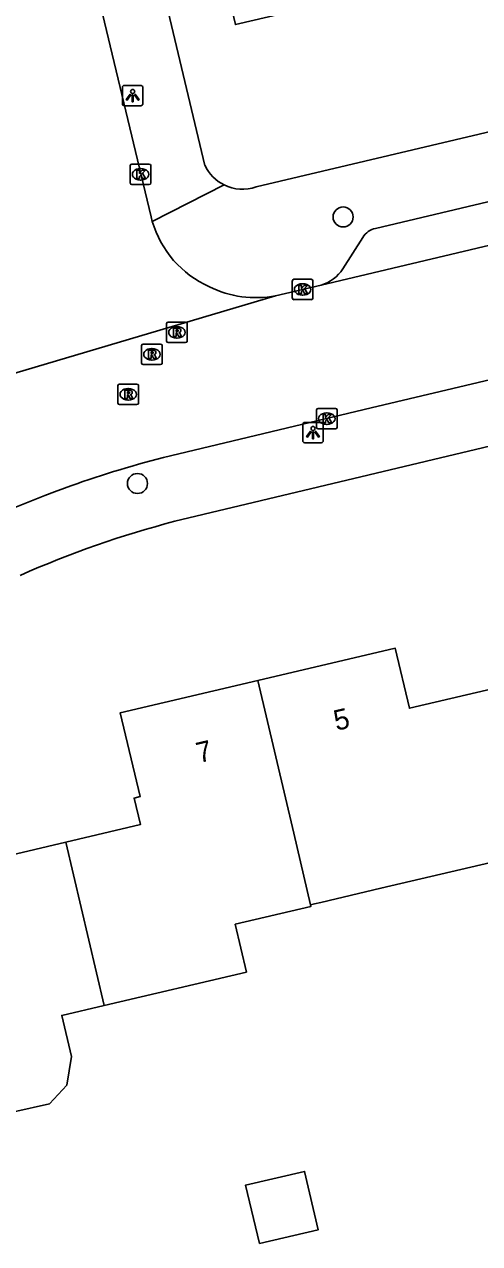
# Model space of a CAD drawing. Extents: x 157663 to 158496, y 379212 to 380934.
# Drawn here: x 158292.8 to 158315.1, y 380647.4 to 380707 of the extents above; entities that cross this region are included whole.
import ezdxf

# ---------------------------------------------------------------- set-up
doc = ezdxf.new("R2010")
doc.units = 0
for name, color, linetype in [('IMGEO_Boom', 7, 'Continuous'), ('IMGEO_Kolk', 7, 'Continuous'), ('IMGEO_Lichtpunt', 7, 'Continuous'), ('IMGEO_Pand', 7, 'Continuous'), ('IMGEO_Pand_nummerreeks', 7, 'Continuous'), ('IMGEO_Rijbaan_lokaal_open', 7, 'Continuous'), ('IMGEO_Rioolput', 7, 'Continuous'), ('IMGEO_Voetpad_open', 7, 'Continuous')]:
    doc.layers.add(name, color=color, linetype=linetype)

msp = doc.modelspace()

# ---------------------------------------------------------------- linework, layer by layer
at = {"layer": 'IMGEO_Boom'}
for centre in [(158308.4, 380697.582), (158298.353, 380684.548)]:
    msp.add_circle(centre, 0.489, dxfattribs=at)
at = {"layer": 'IMGEO_Kolk'}
for p, q in [((158298.004, 380699.245), (158298.004, 380700.097)), ((158298.079, 380700.171), (158298.931, 380700.171)), ((158298.492, 380699.951), (158298.517, 380699.951)), ((158299.005, 380700.097), (158299.005, 380699.245)), ((158298.931, 380699.171), (158298.079, 380699.171)), ((158298.515, 380699.391), (158298.49, 380699.391)), ((158305.919, 380693.613), (158305.919, 380694.465)), ((158305.994, 380694.539), (158306.846, 380694.539)), ((158306.92, 380694.465), (158306.92, 380693.613)), ((158306.407, 380694.319), (158306.432, 380694.319)), ((158306.846, 380693.539), (158305.994, 380693.539)), ((158306.43, 380693.759), (158306.405, 380693.759)), ((158307.102, 380687.294), (158307.102, 380688.146)), ((158307.177, 380688.22), (158308.029, 380688.22)), ((158307.59, 380688), (158307.615, 380688)), ((158308.103, 380688.146), (158308.103, 380687.294)), ((158308.029, 380687.22), (158307.177, 380687.22)), ((158307.613, 380687.44), (158307.588, 380687.44))]:
    msp.add_line(p, q, dxfattribs=at)
for points in [[(158298.004, 380699.245), (158298.004, 380700.097)], [(158298.079, 380700.171), (158298.931, 380700.171)], [(158298.325, 380699.871), (158298.448, 380699.871), (158298.448, 380699.72), (158298.578, 380699.871), (158298.742, 380699.871), (158298.596, 380699.72), (158298.749, 380699.471), (158298.597, 380699.471), (158298.512, 380699.635), (158298.448, 380699.568), (158298.448, 380699.471), (158298.325, 380699.471), (158298.325, 380699.871)], [(158299.005, 380700.097), (158299.005, 380699.245)], [(158298.931, 380699.171), (158298.079, 380699.171)], [(158305.919, 380693.613), (158305.919, 380694.465)], [(158305.994, 380694.539), (158306.846, 380694.539)], [(158306.92, 380694.465), (158306.92, 380693.613)], [(158306.24, 380694.239), (158306.363, 380694.239), (158306.363, 380694.088), (158306.493, 380694.239), (158306.657, 380694.239), (158306.511, 380694.088), (158306.664, 380693.839), (158306.512, 380693.839), (158306.427, 380694.003), (158306.363, 380693.936), (158306.363, 380693.839), (158306.24, 380693.839), (158306.24, 380694.239)], [(158306.846, 380693.539), (158305.994, 380693.539)], [(158307.102, 380687.294), (158307.102, 380688.146)], [(158307.177, 380688.22), (158308.029, 380688.22)], [(158307.423, 380687.92), (158307.546, 380687.92), (158307.546, 380687.769), (158307.676, 380687.92), (158307.84, 380687.92), (158307.694, 380687.769), (158307.847, 380687.52), (158307.695, 380687.52), (158307.61, 380687.684), (158307.546, 380687.617), (158307.546, 380687.52), (158307.423, 380687.52), (158307.423, 380687.92)], [(158308.103, 380688.146), (158308.103, 380687.294)], [(158308.029, 380687.22), (158307.177, 380687.22)]]:
    msp.add_lwpolyline(points, dxfattribs=at)
for centre, start, end in [((158298.081, 380700.095), 91.55205, 178.44795), ((158298.081, 380700.095), 91.55205, 178.44795), ((158298.929, 380700.095), 1.55205, 88.44795), ((158298.929, 380700.095), 1.55205, 88.44795), ((158298.081, 380699.247), 181.55205, 268.44795), ((158298.081, 380699.247), 181.55205, 268.44795), ((158298.929, 380699.247), 271.55205, 358.44795), ((158298.929, 380699.247), 271.55205, 358.44795), ((158305.996, 380694.463), 91.55205, 178.44795), ((158305.996, 380694.463), 91.55205, 178.44795), ((158306.844, 380694.463), 1.55205, 88.44795), ((158306.844, 380694.463), 1.55205, 88.44795), ((158305.996, 380693.615), 181.55205, 268.44795), ((158305.996, 380693.615), 181.55205, 268.44795), ((158306.844, 380693.615), 271.55205, 358.44795), ((158306.844, 380693.615), 271.55205, 358.44795), ((158307.179, 380688.144), 91.55205, 178.44795), ((158307.179, 380688.144), 91.55205, 178.44795), ((158308.027, 380688.144), 1.55205, 88.44795), ((158308.027, 380688.144), 1.55205, 88.44795), ((158307.179, 380687.296), 181.55205, 268.44795), ((158307.179, 380687.296), 181.55205, 268.44795), ((158308.027, 380687.296), 271.55205, 358.44795), ((158308.027, 380687.296), 271.55205, 358.44795)]:
    msp.add_arc(centre, 0.0765, start, end, dxfattribs=at)
for centre, major_axis, ratio, start_param, end_param in [((158298.491, 380699.671), (-0.387, 0.002), 0.722429, 4.712389, 7.853982), ((158298.516, 380699.671), (-0.39, 0.002), 0.717154, 1.570796, 4.712389), ((158306.406, 380694.039), (-0.387, 0.002), 0.722429, 4.712389, 7.853982), ((158306.431, 380694.039), (-0.39, 0.002), 0.717154, 1.570796, 4.712389), ((158307.589, 380687.72), (-0.387, 0.002), 0.722429, 4.712389, 7.853982), ((158307.614, 380687.72), (-0.39, 0.002), 0.717154, 1.570796, 4.712389)]:
    msp.add_ellipse(centre, major_axis=major_axis, ratio=ratio, start_param=start_param, end_param=end_param, dxfattribs=at)
at = {"layer": 'IMGEO_Lichtpunt'}
for p, q in [((158297.619, 380703.921), (158297.619, 380703.114)), ((158297.619, 380703.921), (158297.619, 380703.114)), ((158298.521, 380704.016), (158297.713, 380704.016)), ((158298.521, 380704.016), (158297.713, 380704.016)), ((158298.615, 380703.114), (158298.615, 380703.921)), ((158298.615, 380703.114), (158298.615, 380703.921)), ((158297.713, 380703.02), (158298.521, 380703.02)), ((158297.713, 380703.02), (158298.521, 380703.02)), ((158306.432, 380687.44), (158306.432, 380686.633)), ((158306.432, 380687.44), (158306.432, 380686.633)), ((158307.334, 380687.535), (158306.526, 380687.535)), ((158307.334, 380687.535), (158306.526, 380687.535)), ((158307.428, 380686.633), (158307.428, 380687.44)), ((158307.428, 380686.633), (158307.428, 380687.44)), ((158306.526, 380686.539), (158307.334, 380686.539)), ((158306.526, 380686.539), (158307.334, 380686.539))]:
    msp.add_line(p, q, dxfattribs=at)
for points in [[(158297.993, 380703.585), (158298.032, 380703.557), (158297.844, 380703.295), (158297.806, 380703.322), (158297.993, 380703.585)], [(158298.095, 380703.537), (158298.142, 380703.537), (158298.142, 380703.215), (158298.095, 380703.215), (158298.095, 380703.537)], [(158298.205, 380703.557), (158298.243, 380703.584), (158298.43, 380703.322), (158298.391, 380703.294), (158298.205, 380703.557)], [(158306.806, 380687.104), (158306.845, 380687.076), (158306.657, 380686.814), (158306.619, 380686.841), (158306.806, 380687.104)], [(158306.908, 380687.056), (158306.955, 380687.056), (158306.955, 380686.734), (158306.908, 380686.734), (158306.908, 380687.056)], [(158307.018, 380687.076), (158307.056, 380687.103), (158307.243, 380686.841), (158307.204, 380686.813), (158307.018, 380687.076)]]:
    msp.add_lwpolyline(points, dxfattribs=at)
for centre in [(158298.118, 380703.719), (158306.931, 380687.238)]:
    msp.add_circle(centre, 0.0994, dxfattribs=at)
for centre, start, end in [((158297.713, 380703.921), 90, 180), ((158297.713, 380703.921), 90, 180), ((158298.521, 380703.921), 0, 90), ((158298.521, 380703.921), 0, 90), ((158297.713, 380703.114), 180, 270), ((158297.713, 380703.114), 180, 270), ((158298.521, 380703.114), 270, 0), ((158298.521, 380703.114), 270, 360), ((158306.526, 380687.44), 90, 180), ((158306.526, 380687.44), 90, 180), ((158307.334, 380687.44), 0, 90), ((158307.334, 380687.44), 0, 90), ((158306.526, 380686.633), 180, 270), ((158306.526, 380686.633), 180, 270), ((158307.334, 380686.633), 270, 0), ((158307.334, 380686.633), 270, 360)]:
    msp.add_arc(centre, 0.0946, start, end, dxfattribs=at)
at = {"layer": 'IMGEO_Pand'}
for points in [[(158298.873, 380711.761), (158299.165, 380711.831), (158298.777, 380713.456), (158301.465, 380714.091), (158303.142, 380706.996), (158309.592, 380708.52)], [(158315.674, 380674.501), (158311.638, 380673.553), (158310.947, 380676.493), (158304.231, 380674.916)], [(158304.231, 380674.916), (158297.517, 380673.339), (158298.481, 380669.235), (158298.19, 380669.166), (158298.495, 380667.867), (158294.848, 380667.01)], [(158306.809, 380663.945), (158305.987, 380667.442), (158304.231, 380674.916)], [(158294.848, 380667.01), (158290.91, 380666.085), (158290.21, 380669.064), (158283.396, 380667.463)], [(158294.848, 380667.01), (158296.726, 380659.02)], [(158306.809, 380663.945), (158306.995, 380663.988), (158307.317, 380664.064), (158310.25, 380664.753), (158317.563, 380666.471)], [(158296.726, 380659.02), (158303.678, 380660.653), (158303.128, 380662.996), (158306.828, 380663.864), (158306.809, 380663.945)], [(158285.378, 380659.026), (158285.973, 380656.495), (158289.429, 380657.307), (158289.99, 380654.918), (158290.926, 380654.044), (158292.32, 380653.811), (158294.054, 380654.218), (158294.9, 380655.123), (158295.132, 380656.517), (158294.658, 380658.535), (158296.726, 380659.02)], [(158304.308, 380647.374), (158307.186, 380648.05), (158306.514, 380650.909), (158303.637, 380650.233), (158304.308, 380647.374)]]:
    msp.add_lwpolyline(points, dxfattribs=at)
at = {"layer": 'IMGEO_Rijbaan_lokaal_open'}
for points in [[(158299.078, 380697.367), (158299.024, 380697.594), (158293.7, 380719.842), (158292.832, 380723.522), (158291.886, 380727.513), (158290.986, 380731.308), (158286.732, 380749.252), (158285.857, 380752.928), (158285.387, 380754.879), (158284.513, 380758.542), (158281.657, 380770.677), (158280.79, 380774.351), (158280.032, 380777.559)], [(158387.512, 380706.587), (158352.604, 380698.395), (158345.611, 380696.728), (158333.596, 380693.885), (158329.679, 380692.954), (158315.613, 380689.628), (158309.765, 380688.246), (158299.62, 380685.817)], [(158352.296, 380704.918), (158307.334, 380694.252)], [(158305.104, 380693.726), (158307.334, 380694.252)], [(158288.734, 380688.864), (158305.104, 380693.726)]]:
    msp.add_lwpolyline(points, dxfattribs=at)
for centre, radius, start, end in [((158303.939, 380698.794), 5.067, 196.36278, 245.85659), ((158304.151, 380698.787), 5.15, 243.67605, 280.66884), ((158312.719, 380634.867), 52.607, 104.41786, 109.91778), ((158318.815, 380619.304), 69.317, 110.27292, 117.17225)]:
    msp.add_arc(centre, radius, start, end, dxfattribs=at)
at = {"layer": 'IMGEO_Rioolput'}
for p, q in [((158299.779, 380691.516), (158299.779, 380692.368)), ((158299.854, 380692.442), (158300.706, 380692.442)), ((158300.267, 380692.222), (158300.292, 380692.222)), ((158300.78, 380692.368), (158300.78, 380691.516)), ((158300.706, 380691.442), (158299.854, 380691.442)), ((158300.29, 380691.662), (158300.265, 380691.662)), ((158298.558, 380690.441), (158298.558, 380691.293)), ((158298.633, 380691.367), (158299.485, 380691.367)), ((158299.046, 380691.147), (158299.071, 380691.147)), ((158299.559, 380691.293), (158299.559, 380690.441)), ((158299.485, 380690.367), (158298.633, 380690.367)), ((158299.069, 380690.587), (158299.044, 380690.587)), ((158297.402, 380688.485), (158297.402, 380689.337)), ((158297.477, 380689.411), (158298.329, 380689.411)), ((158297.89, 380689.191), (158297.915, 380689.191)), ((158298.403, 380689.337), (158298.403, 380688.485)), ((158298.329, 380688.411), (158297.477, 380688.411)), ((158297.913, 380688.631), (158297.888, 380688.631))]:
    msp.add_line(p, q, dxfattribs=at)
for points in [[(158299.779, 380691.516), (158299.779, 380692.368)], [(158299.854, 380692.442), (158300.706, 380692.442)], [(158300.368, 380692.14), (158300.116, 380692.142), (158300.116, 380691.742)], [(158300.294, 380692.061), (158300.24, 380692.061), (158300.24, 380691.98)], [(158300.78, 380692.368), (158300.78, 380691.516)], [(158300.706, 380691.442), (158299.854, 380691.442)], [(158300.116, 380691.742), (158300.24, 380691.742), (158300.24, 380691.904), (158300.251, 380691.904)], [(158300.24, 380691.98), (158300.292, 380691.98)], [(158300.298, 380691.875), (158300.369, 380691.742), (158300.509, 380691.742), (158300.444, 380691.868)], [(158298.558, 380690.441), (158298.558, 380691.293)], [(158298.633, 380691.367), (158299.485, 380691.367)], [(158299.147, 380691.065), (158298.895, 380691.067), (158298.895, 380690.667)], [(158298.895, 380690.667), (158299.019, 380690.667), (158299.019, 380690.829), (158299.03, 380690.829)], [(158299.073, 380690.986), (158299.019, 380690.986), (158299.019, 380690.905)], [(158299.019, 380690.905), (158299.071, 380690.905)], [(158299.077, 380690.8), (158299.148, 380690.667), (158299.288, 380690.667), (158299.223, 380690.793)], [(158299.559, 380691.293), (158299.559, 380690.441)], [(158299.485, 380690.367), (158298.633, 380690.367)], [(158297.402, 380688.485), (158297.402, 380689.337)], [(158297.477, 380689.411), (158298.329, 380689.411)], [(158297.991, 380689.109), (158297.739, 380689.111), (158297.739, 380688.711)], [(158297.917, 380689.03), (158297.863, 380689.03), (158297.863, 380688.949)], [(158298.403, 380689.337), (158298.403, 380688.485)], [(158298.329, 380688.411), (158297.477, 380688.411)], [(158297.739, 380688.711), (158297.863, 380688.711), (158297.863, 380688.873), (158297.874, 380688.873)], [(158297.863, 380688.949), (158297.915, 380688.949)], [(158297.921, 380688.844), (158297.992, 380688.711), (158298.132, 380688.711), (158298.067, 380688.837)]]:
    msp.add_lwpolyline(points, dxfattribs=at)
for centre, radius, start, end in [((158299.856, 380692.366), 0.0765, 91.55205, 178.44795), ((158299.856, 380692.366), 0.0765, 91.55205, 178.44795), ((158300.3, 380691.965), 0.0964, 77.00612, 93.18647), ((158300.314, 380692.022), 0.0378, 276.66336, 79.67722), ((158300.367, 380692.03), 0.109, 350.36119, 89.41601), ((158300.365, 380692.03), 0.112, 277.58423, 350.98172), ((158300.704, 380692.366), 0.0765, 1.55205, 88.44795), ((158300.704, 380692.366), 0.0765, 1.55205, 88.44795), ((158299.856, 380691.518), 0.0765, 181.55205, 268.44795), ((158299.856, 380691.518), 0.0765, 181.55205, 268.44795), ((158300.25, 380691.851), 0.0533, 26.02933, 88.69889), ((158300.276, 380692.169), 0.19, 274.7715, 282.96867), ((158300.349, 380691.815), 0.108, 29.51342, 73.79051), ((158300.704, 380691.518), 0.0765, 271.55205, 358.44795), ((158300.704, 380691.518), 0.0765, 271.55205, 358.44795), ((158298.635, 380691.291), 0.0765, 91.55205, 178.44795), ((158298.635, 380691.291), 0.0765, 91.55205, 178.44795), ((158299.029, 380690.776), 0.0533, 26.02933, 88.69889), ((158299.055, 380691.094), 0.19, 274.7715, 282.96867), ((158299.079, 380690.89), 0.0964, 77.00612, 93.18647), ((158299.093, 380690.947), 0.0378, 276.66336, 79.67722), ((158299.146, 380690.955), 0.109, 350.36119, 89.41601), ((158299.144, 380690.955), 0.112, 277.58423, 350.98172), ((158299.128, 380690.74), 0.108, 29.51342, 73.79051), ((158299.483, 380691.291), 0.0765, 1.55205, 88.44795), ((158299.483, 380691.291), 0.0765, 1.55205, 88.44795), ((158298.635, 380690.443), 0.0765, 181.55205, 268.44795), ((158298.635, 380690.443), 0.0765, 181.55205, 268.44795), ((158299.483, 380690.443), 0.0765, 271.55205, 358.44795), ((158299.483, 380690.443), 0.0765, 271.55205, 358.44795), ((158297.479, 380689.335), 0.0765, 91.55205, 178.44795), ((158297.479, 380689.335), 0.0765, 91.55205, 178.44795), ((158297.923, 380688.934), 0.0964, 77.00612, 93.18647), ((158297.937, 380688.991), 0.0378, 276.66336, 79.67722), ((158297.99, 380688.999), 0.109, 350.36119, 89.41601), ((158298.327, 380689.335), 0.0765, 1.55205, 88.44795), ((158298.327, 380689.335), 0.0765, 1.55205, 88.44795), ((158297.479, 380688.487), 0.0765, 181.55205, 268.44795), ((158297.479, 380688.487), 0.0765, 181.55205, 268.44795), ((158297.873, 380688.82), 0.0533, 26.02933, 88.69889), ((158297.899, 380689.138), 0.19, 274.7715, 282.96867), ((158297.988, 380688.999), 0.112, 277.58423, 350.98172), ((158297.972, 380688.784), 0.108, 29.51342, 73.79051), ((158298.327, 380688.487), 0.0765, 271.55205, 358.44795), ((158298.327, 380688.487), 0.0765, 271.55205, 358.44795)]:
    msp.add_arc(centre, radius, start, end, dxfattribs=at)
for centre, major_axis, ratio, start_param, end_param in [((158300.266, 380691.942), (-0.387, 0.002), 0.722429, 4.712389, 7.853982), ((158300.291, 380691.942), (-0.39, 0.002), 0.717154, 1.570796, 4.712389), ((158299.045, 380690.867), (-0.387, 0.002), 0.722429, 4.712389, 7.853982), ((158299.07, 380690.867), (-0.39, 0.002), 0.717154, 1.570796, 4.712389), ((158297.889, 380688.911), (-0.387, 0.002), 0.722429, 4.712389, 7.853982), ((158297.914, 380688.911), (-0.39, 0.002), 0.717154, 1.570796, 4.712389)]:
    msp.add_ellipse(centre, major_axis=major_axis, ratio=ratio, start_param=start_param, end_param=end_param, dxfattribs=at)
at = {"layer": 'IMGEO_Voetpad_open'}
for points in [[(158301.653, 380700.101), (158298.873, 380711.761)], [(158350.686, 380710.073), (158304.146, 380699.056)], [(158309.986, 380697.027), (158318.356, 380699.002), (158322.01, 380699.862), (158348.721, 380706.223)], [(158300.18, 380682.699), (158316.641, 380686.64), (158323.48, 380688.261), (158346.317, 380693.647), (158353.339, 380695.323), (158387.549, 380703.401)], [(158299.078, 380697.367), (158302.589, 380699.148)], [(158308.389, 380695.042), (158309.358, 380696.583)]]:
    msp.add_lwpolyline(points, dxfattribs=at)
for centre, radius, start, end in [((158303.483, 380700.962), 2.022, 205.1959, 243.77287), ((158303.477, 380700.953), 2.012, 243.81278, 289.4241), ((158310.222, 380696.027), 1.028, 103.29413, 147.22698), ((158306.753, 380696.127), 1.963, 287.21448, 326.43837), ((158312.453, 380635.549), 48.721, 104.59035, 114.01743)]:
    msp.add_arc(centre, radius, start, end, dxfattribs=at)

# ---------------------------------------------------------------- texts
at = {"layer": 'IMGEO_Pand_nummerreeks'}
for s, p in [('5', (158308.071, 380672.448)), ('7', (158301.356, 380670.871))]:
    msp.add_text(s, height=1, rotation=13.21814, dxfattribs=at).set_placement(p)

doc.saveas('drawing.dxf')
